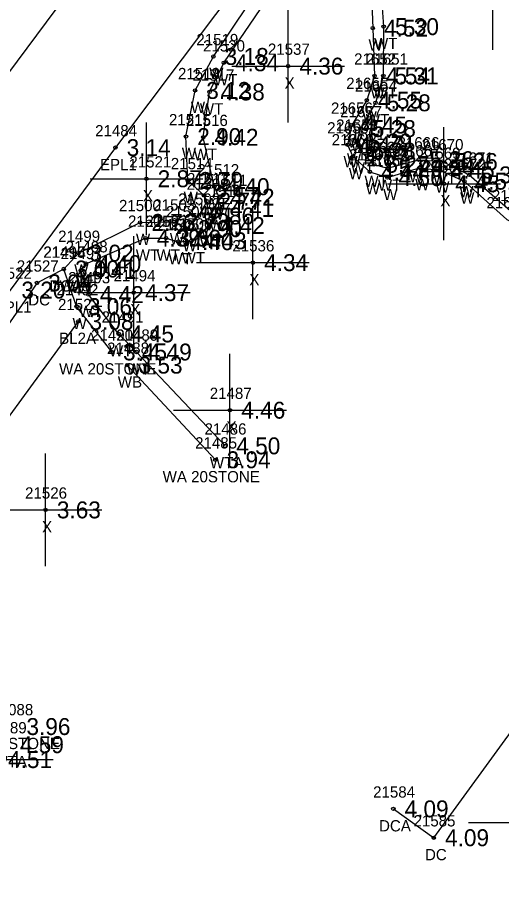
# Model space of a CAD drawing. Extents: x 2608745 to 2610333, y 641917 to 643463.
# Drawn here: x 2610058.8 to 2610101.7, y 642005.8 to 642083.3 of the extents above; entities that cross this region are included whole.
import ezdxf

# ---------------------------------------------------------------- set-up
doc = ezdxf.new("R2010")
doc.units = 0
for name, color, linetype in [('RD_DTM_BkLn1', 7, 'Continuous'), ('RD_DTM_BkLn2', 7, 'Continuous'), ('RD_DTM_BkLn_txCode', 7, 'Continuous'), ('RD_EX_BldgApp', 7, 'Continuous'), ('RD_EX_Conc', 7, 'Continuous'), ('RD_EX_Conc_txCode', 7, 'Continuous'), ('RD_EX_Misc', 7, 'Continuous'), ('RD_EX_Misc_txCode', 7, 'Continuous'), ('RD_EX_Road', 7, 'Continuous'), ('RD_EX_Road_txCode', 7, 'Continuous'), ('RD_EX_TX_Conc_ELEV', 7, 'Continuous'), ('RD_EX_TX_Misc_ELEV', 7, 'Continuous'), ('RD_EX_TX_Road_ELEV', 7, 'Continuous'), ('RD_SMD_Locator', 7, 'Continuous')]:
    doc.layers.add(name, color=color, linetype=linetype)

msp = doc.modelspace()

# ---------------------------------------------------------------- linework, layer by layer
at = {"layer": 'RD_DTM_BkLn1'}
for points in [[(2610092.08, 642124.262), (2610033.919, 642046.064), (2609975.15, 641967.52)], [(2610064.15, 642056.3), (2610053.021, 642041.077), (2610043.709, 642028.432)]]:
    msp.add_lwpolyline(points, dxfattribs=at)
at = {"layer": 'RD_DTM_BkLn2'}
for points in [[(2610077.174, 642045.256), (2610069.318, 642053.582), (2610067.738, 642055.188), (2610065.063, 642058.679), (2610064.383, 642060.822), (2610064.837, 642061.419), (2610070.116, 642063.691), (2610071.947, 642063.685), (2610073.014, 642063.37), (2610074.185, 642063.447), (2610075.79, 642064.803), (2610076.632, 642066.322), (2610076.668, 642067.316), (2610076.224, 642068.252), (2610075.238, 642072.63), (2610075.797, 642076.652), (2610077.057, 642079.242), (2610088.191, 642095.596)], [(2610090.863, 642087.446), (2610091.246, 642082.449), (2610091.217, 642078.074), (2610090.523, 642075.689), (2610089.201, 642073.404), (2610088.847, 642072.21), (2610089.19, 642071.399), (2610090.402, 642070.231), (2610091.598, 642069.881), (2610094.343, 642070.645), (2610096.466, 642070.48), (2610098.82, 642069.296), (2610102.663, 642065.964), (2610105.505, 642064.47), (2610108.443, 642061.709), (2610109.505, 642059.547), (2610109.492, 642057.731)]]:
    msp.add_lwpolyline(points, dxfattribs=at)
at = {"layer": 'RD_EX_BldgApp'}
msp.add_line((2610076.314, 642044.02), (2610068.504, 642052.419), dxfattribs=at)
for points in [[(2610067.124, 642053.588), (2610064.012, 642057.613), (2610062.865, 642060.944), (2610064.164, 642062.352), (2610069.64, 642065.076), (2610072.645, 642065.133), (2610073.768, 642064.527), (2610074.853, 642065.651), (2610075.602, 642066.973), (2610075.309, 642067.463), (2610073.875, 642068.798), (2610073.711, 642072.696), (2610074.512, 642076.786), (2610076.143, 642079.8), (2610087.117, 642096.172)], [(2610090.066, 642087.454), (2610090.275, 642082.315), (2610090.442, 642078.076), (2610089.742, 642075.92), (2610088.411, 642073.718), (2610088.053, 642071.968), (2610088.518, 642070.915), (2610090.02, 642069.577), (2610091.576, 642069.053), (2610094.413, 642069.93), (2610096.189, 642069.722), (2610098.402, 642068.736), (2610102.184, 642065.332), (2610105.016, 642063.884), (2610107.881, 642061.348), (2610108.669, 642059.316), (2610108.72, 642058.165)]]:
    msp.add_lwpolyline(points, dxfattribs=at)
at = {"layer": 'RD_EX_Conc'}
for points in [[(2610062.865, 642060.944), (2610060.494, 642059.714), (2610051.415, 642046.652), (2610037.455, 642028.596), (2610032.589, 642022.148), (2610033.33, 642021.486)], [(2610092.106, 642013.051), (2610095.692, 642010.492), (2610113.596, 642035.061), (2610109.837, 642037.898)]]:
    msp.add_lwpolyline(points, dxfattribs=at)
at = {"layer": 'RD_EX_Misc'}
for p, q in [((2610100.932, 642080.388), (2610100.932, 642090.388)), ((2610082.771, 642073.946), (2610082.771, 642083.946)), ((2610077.771, 642078.946), (2610087.771, 642078.946)), ((2610070.199, 642063.952), (2610070.199, 642073.952)), ((2610096.598, 642063.516), (2610096.598, 642073.516)), ((2610065.199, 642068.952), (2610075.199, 642068.952)), ((2610091.598, 642068.516), (2610101.598, 642068.516)), ((2610079.645, 642056.508), (2610079.645, 642066.508)), ((2610069.079, 642053.848), (2610069.079, 642063.848)), ((2610074.645, 642061.508), (2610084.645, 642061.508)), ((2610064.079, 642058.848), (2610074.079, 642058.848)), ((2610077.614, 642043.419), (2610077.614, 642053.419)), ((2610072.614, 642048.419), (2610082.614, 642048.419)), ((2610061.254, 642034.575), (2610061.254, 642044.575)), ((2610056.254, 642039.575), (2610066.254, 642039.575)), ((2610051.926, 642017.424), (2610061.926, 642017.424)), ((2610098.781, 642011.834), (2610108.781, 642011.834))]:
    msp.add_line(p, q, dxfattribs=at)
at = {"layer": 'RD_EX_Road'}
msp.add_lwpolyline([(2610116.512, 642103.007), (2610109.419, 642106.335), (2610102.937, 642107.104), (2610095.974, 642105.732), (2610091.028, 642103.088), (2610067.446, 642071.713), (2610058.11, 642059.075), (2610043.044, 642039.371), (2610035.942, 642029.795), (2610030.832, 642022.851), (2609999.348, 641980.077), (2609984.87, 641960.622)], dxfattribs=at)
at = {"layer": 'RD_SMD_Locator'}
for centre in [(2610090.275, 642082.315), (2610091.246, 642082.449), (2610076.143, 642079.8), (2610077.057, 642079.242), (2610082.771, 642078.946), (2610090.442, 642078.076), (2610091.217, 642078.074), (2610074.512, 642076.786), (2610075.797, 642076.652), (2610089.742, 642075.92), (2610090.523, 642075.689), (2610088.411, 642073.718), (2610089.201, 642073.404), (2610073.711, 642072.696), (2610075.238, 642072.63), (2610067.446, 642071.713), (2610088.053, 642071.968), (2610088.847, 642072.21), (2610088.518, 642070.915), (2610089.19, 642071.399), (2610090.402, 642070.231), (2610094.343, 642070.645), (2610094.413, 642069.93), (2610096.466, 642070.48), (2610090.02, 642069.577), (2610091.598, 642069.881), (2610096.189, 642069.722), (2610098.82, 642069.296), (2610070.199, 642068.952), (2610073.875, 642068.798), (2610091.576, 642069.053), (2610096.598, 642068.516), (2610098.402, 642068.736), (2610076.224, 642068.252), (2610075.309, 642067.463), (2610075.602, 642066.973), (2610076.668, 642067.316), (2610076.632, 642066.322), (2610074.853, 642065.651), (2610069.64, 642065.076), (2610072.645, 642065.133), (2610073.768, 642064.527), (2610075.79, 642064.803), (2610070.116, 642063.691), (2610071.947, 642063.685), (2610073.014, 642063.37), (2610074.185, 642063.447), (2610064.164, 642062.352), (2610064.837, 642061.419), (2610079.645, 642061.508), (2610062.865, 642060.944), (2610062.865, 642060.944), (2610064.383, 642060.822), (2610060.494, 642059.714), (2610065.063, 642058.679), (2610069.079, 642058.848), (2610064.012, 642057.613), (2610064.15, 642056.3), (2610067.738, 642055.188), (2610067.124, 642053.588), (2610069.318, 642053.582), (2610068.504, 642052.419), (2610077.614, 642048.419), (2610077.174, 642045.256), (2610076.314, 642044.02), (2610061.254, 642039.575), (2610092.106, 642013.051), (2610095.692, 642010.492)]:
    msp.add_circle(centre, 0.15, dxfattribs=at)

# ---------------------------------------------------------------- texts
at = {"layer": 'RD_DTM_BkLn_txCode'}
for s, p in [('21523', (2610062.355, 642057.3)), ('BL2A', (2610062.457, 642054.3))]:
    msp.add_text(s, height=1, dxfattribs=at).set_placement(p)
at = {"layer": 'RD_EX_Conc_txCode'}
for s, p in [('21496', (2610061.047, 642061.944)), ('21527', (2610058.699, 642060.714)), ('DCA', (2610061.598, 642058.944)), ('DC', (2610059.715, 642057.714)), ('21584', (2610090.311, 642014.051)), ('DCA', (2610090.838, 642011.051)), ('21585', (2610093.896, 642011.492)), ('DC', (2610094.912, 642008.492))]:
    msp.add_text(s, height=1, dxfattribs=at).set_placement(p)
at = {"layer": 'RD_EX_Misc_txCode'}
for s, p in [('21519', (2610074.631, 642080.8)), ('21520', (2610075.222, 642080.242)), ('21537', (2610080.976, 642079.946)), ('W', (2610089.905, 642080.315)), ('WT', (2610090.388, 642080.449)), ('21652', (2610088.624, 642079.076)), ('21651', (2610089.681, 642079.074)), ('21518', (2610073, 642077.786)), ('21517', (2610074.285, 642077.652)), ('W', (2610075.772, 642077.8)), ('WT', (2610076.198, 642077.242)), ('X', (2610082.456, 642076.946)), ('21655', (2610087.923, 642076.92)), ('21654', (2610088.705, 642076.689)), ('W', (2610090.072, 642076.076)), ('WT', (2610090.358, 642076.074)), ('W', (2610074.142, 642074.786)), ('WT', (2610074.939, 642074.652)), ('21656', (2610086.569, 642074.718)), ('21657', (2610087.382, 642074.404)), ('W', (2610089.372, 642073.92)), ('21515', (2610072.199, 642073.696)), ('21516', (2610073.703, 642073.63)), ('21659', (2610086.234, 642072.968)), ('21658', (2610087.028, 642073.21)), ('WT', (2610089.665, 642073.689)), ('21661', (2610087.631, 642072.399)), ('21660', (2610086.636, 642071.915)), ('W', (2610088.041, 642071.718)), ('WT', (2610088.343, 642071.404)), ('21666', (2610092.477, 642071.645)), ('21670', (2610094.608, 642071.48)), ('W', (2610073.341, 642070.696)), ('WT', (2610074.38, 642070.63)), ('21662', (2610088.559, 642071.231)), ('21665', (2610089.755, 642070.881)), ('21667', (2610092.57, 642070.93)), ('21669', (2610094.347, 642070.722)), ('21521', (2610068.687, 642069.952)), ('W', (2610087.682, 642069.968)), ('WT', (2610087.988, 642070.21)), ('21663', (2610088.177, 642070.577)), ('21664', (2610089.733, 642070.053)), ('21671', (2610097.285, 642070.296)), ('21514', (2610072.363, 642069.798)), ('21512', (2610074.712, 642069.252)), ('WT', (2610088.331, 642069.399)), ('21668', (2610094.755, 642069.516)), ('21672', (2610096.583, 642069.736)), ('21513', (2610073.797, 642068.463)), ('21511', (2610075.439, 642068.316)), ('W', (2610088.148, 642068.915)), ('WT', (2610093.484, 642068.645)), ('WT', (2610095.608, 642068.48)), ('21509', (2610073.767, 642067.973)), ('WT', (2610089.543, 642068.231)), ('W', (2610089.65, 642067.577)), ('WT', (2610090.739, 642067.881)), ('W', (2610094.043, 642067.93)), ('W', (2610095.819, 642067.722)), ('X', (2610069.884, 642066.952)), ('W', (2610073.505, 642066.798)), ('21510', (2610075.081, 642067.322)), ('W', (2610091.206, 642067.053)), ('WT', (2610097.962, 642067.296)), ('21674', (2610100.844, 642066.964)), ('21500', (2610067.766, 642066.076)), ('21503', (2610070.81, 642066.133)), ('21508', (2610073.019, 642066.651)), ('WT', (2610075.366, 642066.252)), ('X', (2610096.283, 642066.516)), ('W', (2610098.031, 642066.736)), ('21673', (2610100.365, 642066.332)), ('21504', (2610071.934, 642065.527)), ('21507', (2610073.956, 642065.803)), ('W', (2610074.939, 642065.463)), ('WT', (2610075.81, 642065.316)), ('21501', (2610068.565, 642064.691)), ('21502', (2610070.112, 642064.685)), ('21506', (2610072.326, 642064.447)), ('W', (2610075.232, 642064.973)), ('21505', (2610071.18, 642064.37)), ('W', (2610074.483, 642063.651)), ('WT', (2610075.774, 642064.322)), ('21499', (2610062.369, 642063.352)), ('W', (2610069.27, 642063.076)), ('W', (2610072.275, 642063.133)), ('21498', (2610063.042, 642062.419)), ('W', (2610073.398, 642062.527)), ('WT', (2610074.932, 642062.803)), ('21536', (2610077.826, 642062.508)), ('21495', (2610061.07, 642061.944)), ('21497', (2610062.588, 642061.822)), ('WT', (2610069.258, 642061.691)), ('WT', (2610071.088, 642061.685)), ('WT', (2610072.156, 642061.37)), ('WT', (2610073.326, 642061.447)), ('W', (2610063.794, 642060.352)), ('21494', (2610067.284, 642059.848)), ('21493', (2610063.268, 642059.679)), ('WT', (2610063.979, 642059.419)), ('X', (2610079.33, 642059.508)), ('21492', (2610062.217, 642058.613)), ('W', (2610062.495, 642058.944)), ('WT', (2610063.525, 642058.822)), ('X', (2610068.764, 642056.848)), ('WT', (2610064.205, 642056.679)), ('21491', (2610066.226, 642056.188)), ('W', (2610063.642, 642055.613)), ('21490', (2610065.29, 642054.588)), ('21489', (2610067.523, 642054.582)), ('21488', (2610066.709, 642053.419)), ('WT', (2610066.88, 642053.188)), ('WA 20STONE', (2610062.451, 642051.588)), ('WT', (2610068.46, 642051.582)), ('WB', (2610067.662, 642050.419)), ('21487', (2610075.818, 642049.419)), ('21486', (2610075.355, 642046.256)), ('X', (2610077.299, 642046.419)), ('21485', (2610074.519, 642045.02)), ('WTA', (2610075.827, 642043.256)), ('WA 20STONE', (2610071.641, 642042.02)), ('21526', (2610059.435, 642040.575)), ('X', (2610060.939, 642037.575)), ('22088', (2610056.439, 642021.354)), ('22089', (2610055.859, 642019.749)), ('WA 1STONE', (2610054.655, 642018.354)), ('WTA', (2610056.631, 642016.749))]:
    msp.add_text(s, height=1, dxfattribs=at).set_placement(p)
at = {"layer": 'RD_EX_Road_txCode'}
for s, p in [('21484', (2610065.651, 642072.713)), ('EPL1', (2610066.076, 642069.713)), ('21522', (2610056.314, 642060.075)), ('EPL1', (2610056.74, 642057.075))]:
    msp.add_text(s, height=1, dxfattribs=at).set_placement(p)
at = {"layer": 'RD_EX_TX_Conc_ELEV'}
for s, p in [('3.00', (2610063.865, 642060.194)), ('3.04', (2610061.494, 642058.964)), ('4.09', (2610093.106, 642012.301)), ('4.09', (2610096.692, 642009.742))]:
    msp.add_text(s, height=1.5, dxfattribs=at).set_placement(p)
at = {"layer": 'RD_EX_TX_Misc_ELEV'}
for s, p in [('4.52', (2610091.275, 642081.565)), ('5.30', (2610092.246, 642081.699)), ('3.18', (2610077.143, 642079.05)), ('4.34', (2610078.057, 642078.492)), ('4.36', (2610083.771, 642078.196)), ('4.54', (2610091.442, 642077.326)), ('5.31', (2610092.217, 642077.324)), ('3.12', (2610075.512, 642076.036)), ('4.38', (2610076.797, 642075.902)), ('4.55', (2610090.742, 642075.17)), ('5.28', (2610091.523, 642074.939)), ('4.45', (2610089.411, 642072.968)), ('5.28', (2610090.201, 642072.654)), ('2.90', (2610074.711, 642071.946)), ('4.42', (2610076.238, 642071.88)), ('4.47', (2610089.053, 642071.218)), ('5.29', (2610089.847, 642071.46)), ('4.57', (2610089.518, 642070.165)), ('5.28', (2610090.19, 642070.649)), ('5.27', (2610091.402, 642069.481)), ('5.26', (2610095.343, 642069.895)), ('5.26', (2610097.466, 642069.73)), ('4.44', (2610091.02, 642068.827)), ('5.29', (2610092.598, 642069.131)), ('4.54', (2610095.413, 642069.18)), ('4.45', (2610097.189, 642068.972)), ('2.87', (2610071.199, 642068.202)), ('2.79', (2610074.875, 642068.048)), ('4.56', (2610092.576, 642068.303)), ('4.51', (2610099.402, 642067.986)), ('5.31', (2610099.82, 642068.546)), ('4.40', (2610077.224, 642067.502)), ('4.45', (2610097.598, 642067.766)), ('2.57', (2610076.309, 642066.713)), ('4.42', (2610077.668, 642066.566)), ('2.77', (2610076.602, 642066.223)), ('4.41', (2610077.632, 642065.572)), ('2.86', (2610075.853, 642064.901)), ('2.76', (2610070.64, 642064.326)), ('2.73', (2610073.645, 642064.383)), ('4.42', (2610076.79, 642064.053)), ('2.90', (2610074.768, 642063.777)), ('4.39', (2610071.116, 642062.941)), ('3.39', (2610072.947, 642062.935)), ('4.40', (2610074.014, 642062.62)), ('4.43', (2610075.185, 642062.697)), ('3.02', (2610065.164, 642061.602)), ('3.00', (2610063.865, 642060.194)), ('4.41', (2610065.383, 642060.072)), ('4.40', (2610065.837, 642060.669)), ('4.34', (2610080.645, 642060.758)), ('4.42', (2610066.063, 642057.929)), ('4.37', (2610070.079, 642058.098)), ('3.06', (2610065.012, 642056.863)), ('3.08', (2610065.15, 642055.55)), ('4.45', (2610068.738, 642054.438)), ('3.45', (2610068.124, 642052.838)), ('4.49', (2610070.318, 642052.832)), ('3.53', (2610069.504, 642051.669)), ('4.46', (2610078.614, 642047.669)), ('4.50', (2610078.174, 642044.506)), ('3.94', (2610077.314, 642043.27)), ('3.63', (2610062.254, 642038.825)), ('3.96', (2610059.557, 642019.604)), ('4.59', (2610058.977, 642017.999)), ('4.51', (2610057.926, 642016.674))]:
    msp.add_text(s, height=1.5, dxfattribs=at).set_placement(p)
at = {"layer": 'RD_EX_TX_Road_ELEV'}
for s, p in [('3.14', (2610068.446, 642070.963)), ('3.20', (2610059.11, 642058.325))]:
    msp.add_text(s, height=1.5, dxfattribs=at).set_placement(p)

doc.saveas('drawing.dxf')
